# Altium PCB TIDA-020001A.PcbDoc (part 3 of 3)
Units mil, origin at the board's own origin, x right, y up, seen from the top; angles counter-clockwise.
Board outline 11050 x 5518 mil, 4 copper layers (Top Layer, PWR, GND, Bottom Layer), stack 61.434 mil thick; 283 components, 210 nets, 883 pads, 1184 vias.
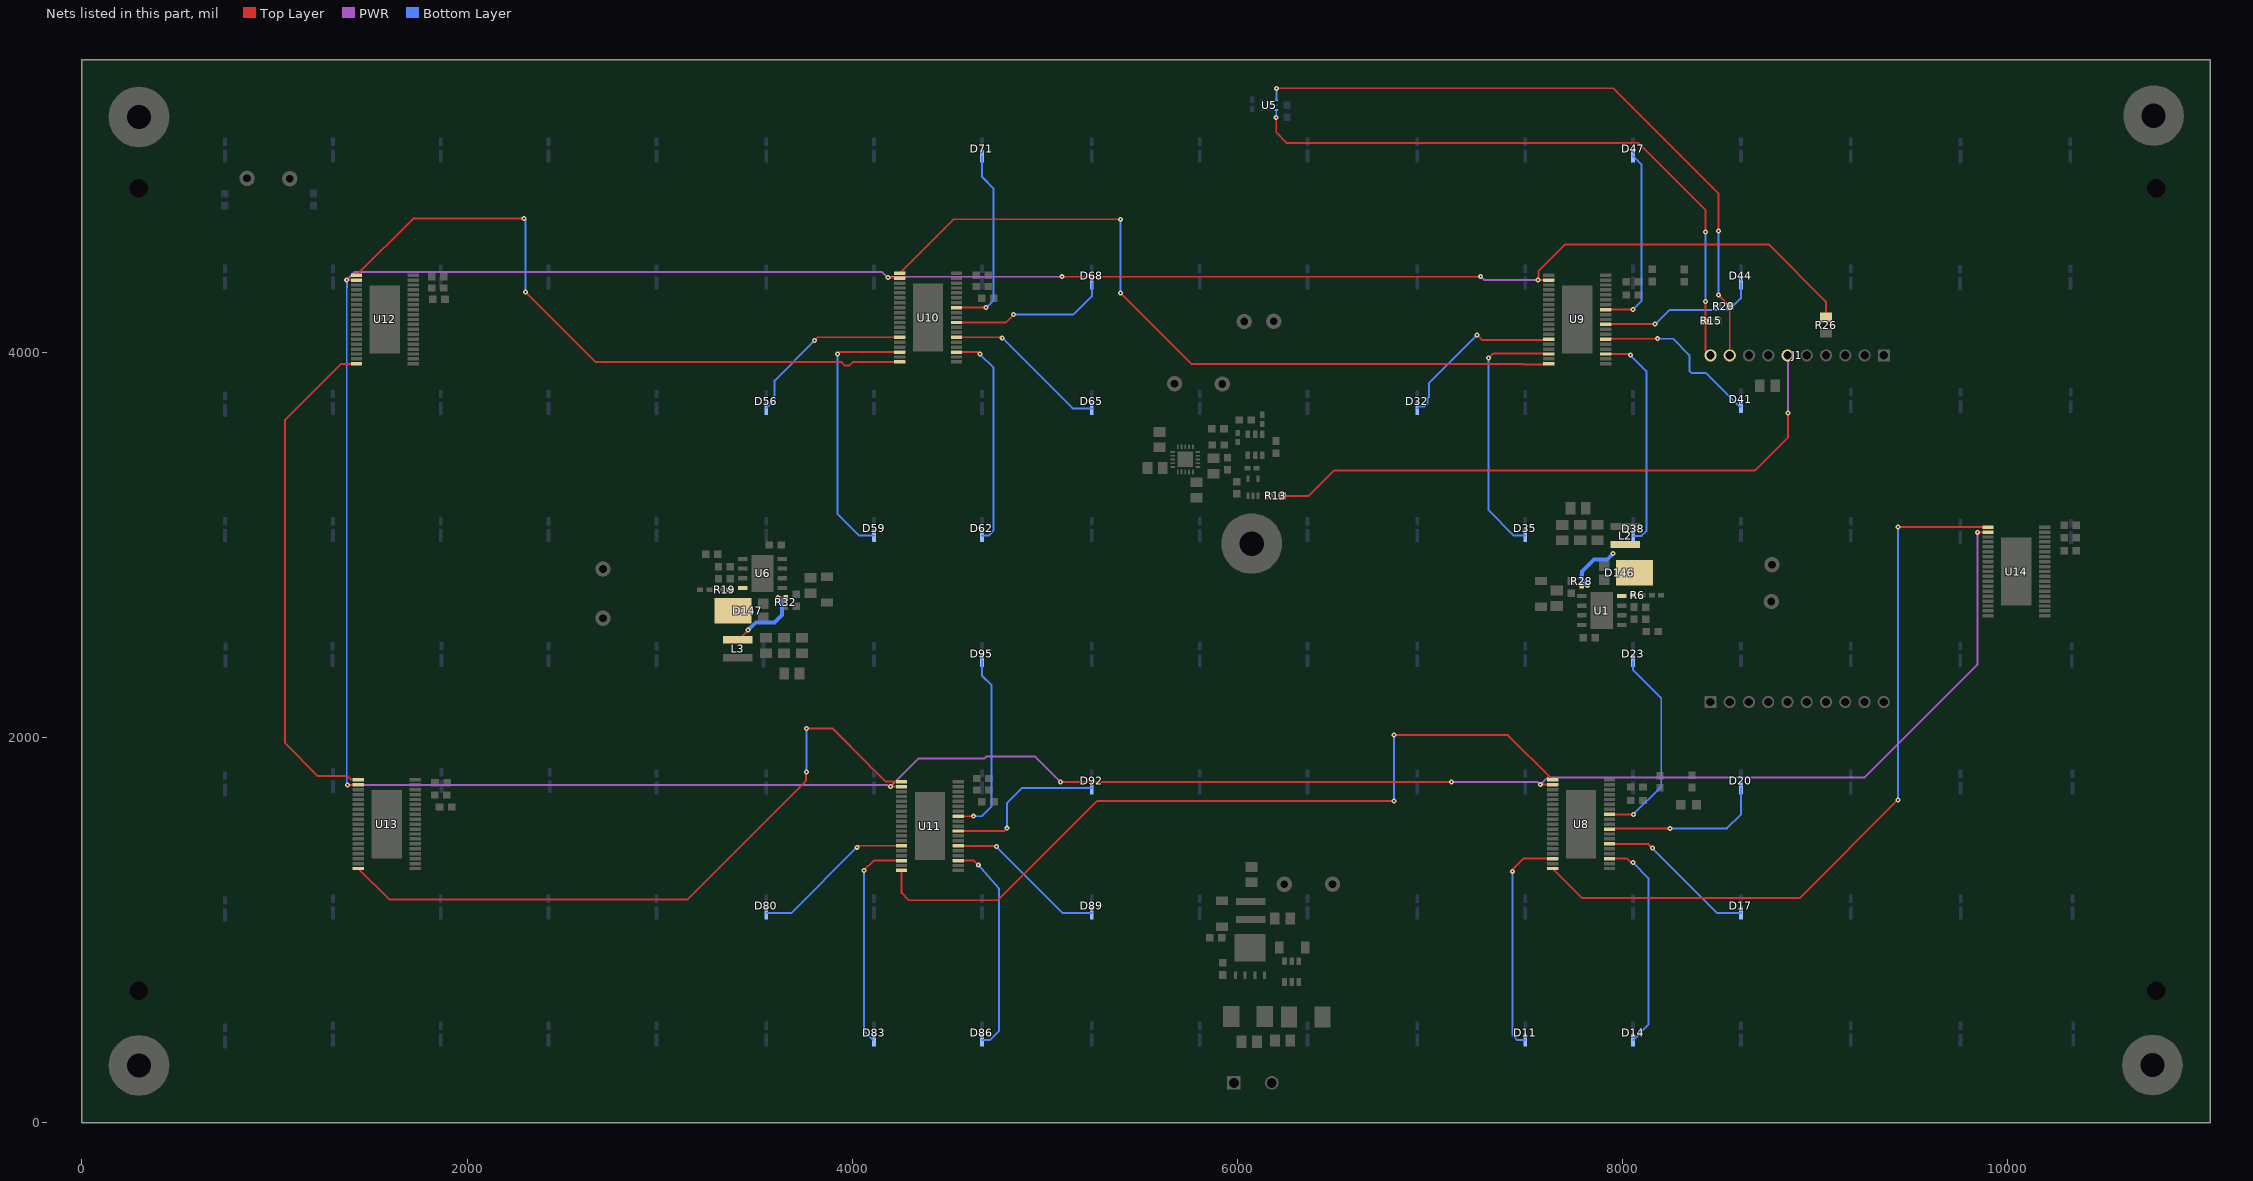
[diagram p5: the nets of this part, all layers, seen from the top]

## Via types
v1: diameter 20, hole 10, Top Layer to Bottom Layer, tented both sides, 504 vias
v2: diameter 26, hole 10, Top Layer to Bottom Layer, tented both sides, 472 vias
v3: diameter 19.68, hole 7.87, Top Layer to Bottom Layer, tented both sides, 205 vias
v4: diameter 34, hole 16, Top Layer to Bottom Layer, tented both sides, 2 vias
v5: diameter 19.68, hole 7.87, Top Layer to Bottom Layer, 1 vias

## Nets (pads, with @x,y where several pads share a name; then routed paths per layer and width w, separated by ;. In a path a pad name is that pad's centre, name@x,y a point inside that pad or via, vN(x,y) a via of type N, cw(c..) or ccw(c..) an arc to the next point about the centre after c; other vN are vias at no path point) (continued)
OUTR2/1: D32.1 U9.14 | length 911.9
  Top Layer w10: v2(7243.56,4089.71) 7270.99,4062.28 7580.99,4062.28 7582.2,4063.49 7612.07,4063.49 U9.14@7615.92,4067.35
  Bottom Layer w10: D32.1@6933.56,3708.21 6943.35,3718 6971,3718 6986.56,3733.56 6986.56,3761.21 6993.56,3768.21 6993.56,3839.71 v2(7243.56,4089.71)
OUTR2/2: D56.1 U10.14 | length 903.2
  Top Layer w10: v2(3803.56,4059.71) 3821.2,4077.35 U10.14@4245.92,4077.35
  Bottom Layer w10: D56.1@3553.56,3709.71 3596.43,3752.58 3596.43,3852.58 v2(3803.56,4059.71)
OUTR2/3: D80.1 U11.14 | length 847.2
  Top Layer w10: v2@4023.71,1429.71 v2(4023.56,1429.71) v2@4031.82,1437.97 ; v2@4032,1438 U11.14@4255.92,1437.35
  Bottom Layer w10: D80.1@3553.56,1088.21 3682.06,1088.21 v2(4023.56,1429.71)
OUTR3: D11.1 U8.17 | length 1171.5
  Top Layer w10: v2(7428.17,1305.1) 7423.56,1309.71 7484.43,1370.58 U8.17@7635.92,1370.58
  Bottom Layer w10: v2(7428.17,1305.1) 7428.17,453.6 7453.56,428.21 D11.1@7493.56,428.21
OUTR3/1: D35.1 U9.17 | length 1358.3
  Top Layer w10: v2(7303.56,3969.71) 7327.84,3993.99 7612.51,3993.99 U9.17@7615.92,3990.58
  Bottom Layer w10: v2(7303.56,3969.71) 7303.56,3179.71 7435.06,3048.22 D35.1@7493.56,3048.22
OUTR3/2: D59.1 U10.17 | length 1393
  Top Layer w10: v2(3923.56,3989.71) 3934.43,4000.58 U10.17@4245.92,4000.58
  Bottom Layer w10: v2(3923.56,3989.71) 3923.56,3159.71 4035.06,3048.21 D59.1@4113.56,3048.21
OUTR3/3: D83.1 U11.17 | length 1118.1
  Top Layer w10: v2(4060.41,1309.71) 4111.28,1360.58 U11.17@4255.92,1360.58
  Bottom Layer w10: v2(4060.41,1309.71) 4060.41,476.56 D83.1@4108.76,428.21
OUTR4: D14.1 U8.22 | length 1118.8
  Top Layer w10: U8.22@7931.2,1370.58 8022.69,1370.58 8043.56,1349.71 v2(8053.56,1349.71)
  Bottom Layer w10: D14.1@8053.56,428.21 8133.56,508.21 8133.56,1269.71 v2(8053.56,1349.71)
OUTR4/1: D38.1 U9.22 | length 1155.3
  Top Layer w10: U9.22@7911.2,3990.58 8033.83,3990.58 v2(8039.64,3984.76)
  Bottom Layer w10: v2(8039.64,3984.76) 8123.03,3901.37 8123.03,3075.77 ; D38.1@8054.9,3046.55 8096.81,3046.55 8124.37,3074.1
OUTR4/2: D62.1 U10.22 | length 1142.3
  Top Layer w10: U10.22@4541.2,4000.58 4541.61,4000.98 4641.73,4000 4652.56,4000 v2(4662.4,3990.16)
  Bottom Layer w10: v2(4662.4,3990.16) 4734.25,3918.31 4734.25,3074.8 4707.66,3048.21 D62.1@4673.56,3048.21
OUTR4/3: D86.1 U11.22 | length 1133.5
  Top Layer w10: U11.22@4551.2,1360.58 4631.68,1360.58 v2(4654.25,1338)
  Bottom Layer w10: v2@4646.31,1330.2 v2@4654.12,1338 ; v2(4654.25,1338) v2@4654.12,1338 ; D86.1@4673.56,428.21 4713.65,428.21 4760.83,475.39 4760.83,1216.54 4759.98,1216.54 v2@4654.12,1338
OUTR5: D17.1 U8.25 | length 831.1
  Top Layer w10: U8.25@7931.2,1447.35 8131.2,1447.35 v2(8153.56,1424.99)
  Bottom Layer w10: v2(8153.56,1424.99) 8490.33,1088.21 D17.1@8613.56,1088.21
OUTR5/1: D41.1 U9.25 | length 896.4
  Top Layer w10: U9.25@7911.2,4067.35 v2(8180.12,4069.88)
  Bottom Layer w10: v2(8180.12,4069.88) 8261.89,4069.88 8346.56,3985.21 8346.56,3902.67 8356.52,3892.71 8431.38,3892.71 8605.87,3718.21 D41.1@8613.56,3718.21
OUTR5/2: D65.1 U10.25 | length 855.3
  Top Layer w10: U10.25@4541.2,4077.35 4775.01,4077.35 v2(4778.54,4073.82)
  Bottom Layer w10: v2(4778.54,4073.82) 5144.15,3708.21 D65.1@5243.56,3708.21
OUTR5/3: D89.1 U11.25 | length 837
  Top Layer w10: U11.25@4551.2,1437.35 4744.06,1437.35 v2(4748.26,1433.14)
  Bottom Layer w10: v2(4748.26,1433.14) 5093.19,1088.21 D89.1@5243.56,1088.21
OUTR6: D20.1 U8.28 | length 852.1
  Top Layer w10: U8.28@7931.2,1524.12 7934.61,1527.53 v2(8245.05,1527.53)
  Bottom Layer w10: v2(8245.05,1527.53) 8540.32,1527.53 8614.17,1601.38 8614.17,1737.6 D20.1@8613.56,1738.21
OUTR6/1: D44.1 U9.28 | length 837
  Top Layer w10: U9.28@7911.2,4144.12 7913.93,4146.86 v2(8167.72,4146.86)
  Bottom Layer w10: v2(8167.72,4146.86) 8170.71,4146.86 8243.56,4219.71 8553.56,4219.71 8613.56,4279.71 D44.1@8613.56,4358.21
OUTR6/2: D68.1 U10.28 | length 828.8
  Top Layer w10: U10.28@4541.2,4154.12 4797.97,4154.12 4808.6,4164.75 4808.6,4165.56 4825.59,4182.54 4826.39,4182.54 4837.6,4193.75 v2(4837.6,4195.91)
  Bottom Layer w10: v2(4837.6,4195.91) 5149.76,4195.91 5223.56,4269.71 5243.56,4289.71 D68.1@5243.56,4358.22
OUTR6/3: D92.1 U11.28 | length 862
  Top Layer w10: U11.28@4551.2,1514.12 4789.15,1514.12 v2(4803.56,1528.53)
  Bottom Layer w10: v2(4803.56,1528.53) 4803.56,1659.71 4882.06,1738.21 D92.1@5243.56,1738.21
OUTR7: D23.1 U8.31 | length 1041.4
  Top Layer w10: U8.31@7931.2,1600.89 8054.62,1600.89 v2(8055.12,1600.39)
  Bottom Layer w10: D23.1@8054.27,2397.5 8054.27,2349 8199.8,2203.47 8199.8,1745.08 v2(8055.12,1600.39)
OUTR7/1: D47.1 U9.31 | length 974.5
  Top Layer w10: U9.31@7911.2,4220.89 v2(8052.38,4220.89)
  Bottom Layer w10: v2(8052.38,4220.89) 8096.43,4264.95 8096.43,4975.34 D47.1@8053.56,5018.21
OUTR7/2: D71.1 U10.31 | length 981.8
  Top Layer w10: U10.31@4541.2,4230.89 v2(4694.74,4230.89)
  Bottom Layer w10: D71.1@4673.56,5018.22 4673.56,4909.71 4733.56,4849.71 4733.56,4269.71 v2(4694.74,4230.89)
OUTR7/3: D95.1 U11.31 | length 970.4
  Top Layer w10: U11.31@4551.2,1590.89 v2(4628.94,1590.89)
  Bottom Layer w10: v2(4628.94,1590.89) 4672.38,1590.89 4723.56,1642.07 4723.56,2269.71 4673.56,2319.71 D95.1@4673.56,2398.21
SCK: R26.1 U8.2 U9.2 U10.2 U11.2 U12.2 U13.2 U14.2 | length 20609.9
  Top Layer w10: v2(1375.59,4374.72) 1425.64,4374.72 U12.2@1425.92,4374.43 ; v2(1379.92,1753.94) 1427.52,1753.94 1428.59,1755.01 1432.54,1751.05 U13.2@1435.92,1754.43 ; v2(4185.24,4388.01) 4242.35,4388.01 U10.2@4245.92,4384.43 ; v2(4197.83,1745.08) 4255.28,1745.08 U11.2@4255.92,1744.43 ; v2(5081.69,1767.72) v2(7110.24,1767.72) ; v2(5089.57,4391.73) 7261.81,4391.73 7262.8,4390.75 v2(7262.8,4392.72) ; v2@7561.02,4386.93 v2(7561.02,4375) 7615.36,4375 U9.2@7615.92,4374.43 ; v2@7561.86,4386.96 7561.86,4420.13 7700.79,4559.06 8758.86,4559.06 9055.12,4262.8 9055.12,4181.09 R26.1@9055.92,4180.3 ; v2(7571.85,1754.92) 7635.44,1754.92 U8.2@7635.92,1754.43 ; v2(9842.52,3064.96) 9888.65,3064.96 9892.89,3069.2 U14.2@9896.04,3066.05
  PWR w10: v2(1375.59,4374.72) 1418.19,4417.32 4152.56,4417.32 4186.02,4383.86 4185.04,4383.86 4185.24,4384.06 v2(4185.24,4388.01) 4188.97,4391.73 v2(5089.57,4391.73) ; v2(1379.92,1753.94) 4181.07,1753.94 4189.92,1745.08 v2(4197.83,1745.08) 4342.91,1890.16 4684.57,1890.16 4695,1900.59 4948.82,1900.59 v2(5081.69,1767.72) ; v2(7110.24,1767.72) 7559.06,1767.72 v2(7571.85,1754.92) 7609.9,1792.97 9256.48,1792.97 9842.52,2379.01 v2(9842.52,3064.96) ; v2(7262.8,4392.72) 7280.51,4375 v2(7561.02,4375)
  Bottom Layer w10: v2(1375.59,4374.72) 1375.59,4360.56 1377.36,4358.78 1377.36,4338.07 1375.59,4336.29 1375.59,1758.27 v2@1382.81,1751.05 ; v2(7571.85,1754.92) v2@7574.8,1757.87
SCLA: J1.9 R20.1 U5.4 | length 3452.5
  Top Layer w10: v2(6201.77,5370.08) 7949.8,5370.08 8498.03,4821.85 v2(8498.03,4628.94) ; v2(8498.03,4296.26) 8555.68,4238.61 J1.9@8555.68,3983.33
  Bottom Layer w10: U5.4@6201.03,5307.83 6201.77,5308.57 v2(6201.77,5370.08) ; v2(8498.03,4628.94) v2(8498.03,4296.26) v2@8500.98,4293.31
SDAA: J1.10 R15.1 U5.6 | length 3277.6
  Top Layer w10: v2(6201.03,5217.52) 6201.03,5141.49 6256.89,5085.63 8082.68,5085.63 8429.13,4739.17 8429.13,4624.02 v2(8430.12,4623.03) ; v2(8429.13,4262.8) R15.1@8429.13,4162.4 8429.13,4009.87 J1.10@8455.68,3983.33
  Bottom Layer w10: v2(6201.03,5217.52) U5.6@6201.03,5256.65 ; v2(8429.13,4262.8) 8430.12,4263.78 v2(8430.12,4623.03)
SDO8/SDI14: U8.19 U14.1 | length 3952.8
  Top Layer w10: U8.19@7635.92,1319.4 7789.97,1165.35 8918.31,1165.35 v2(9428.15,1675.2) ; v2(9428.15,3091.54) 9428.15,3092.52 9429.03,3091.64 U14.1@9896.04,3091.64
  Bottom Layer w10: v2(9428.15,1675.2) v2(9428.15,3091.54)
SDO9/SDI10: U9.19 U10.1 | length 4025.4
  Top Layer w10: U10.1@4245.92,4410.03 4525.86,4689.96 v2(5391.73,4689.96) ; v2(5391.73,4308.07) 5760.41,3939.4 7481.58,3939.4 7484.99,3935.99 7615.92,3935.99 U9.19@7615.92,3939.4
  Bottom Layer w10: v2(5391.73,4308.07) v2(5391.73,4689.96)
SDO10/SDI12: U10.19 U12.1 | length 3484.7
  Top Layer w10: U12.1@1425.92,4400.03 1719.8,4693.9 v2(2296.26,4693.9) ; v2(2304.13,4312.01) 2666.75,3949.4 3942.86,3949.4 3961.55,3930.71 3985.57,3930.71 4004.26,3949.4 U10.19@4245.92,3949.4
  Bottom Layer w10: v2(2296.26,4693.9) 2304.13,4686.02 v2(2304.13,4312.01)
SDO11/SDI8: U8.1 U11.19 | length 4163
  Top Layer w10: U11.19@4255.92,1309.4 4255.92,1192.9 4294.29,1154.53 4755.91,1154.53 5271.65,1670.28 v2(6812.01,1670.28) ; v2(6812.99,2011.81) 7404.14,2011.81 U8.1@7635.92,1780.03
  Bottom Layer w10: v2(6812.01,1670.28) 6812.99,1671.26 v2(6812.99,2011.81)
SDO12/SDI13: U12.19 U13.1 | length 2629.3
  Top Layer w10: U12.19@1425.92,3939.4 1346.88,3939.4 1054.13,3646.65 1054.13,1971.46 1225.98,1799.61 1378.54,1799.61 1398.12,1780.03 U13.1@1435.92,1780.03
SDO13/SDI11: U11.1 U13.19 | length 3529.2
  Top Layer w10: U13.19@1435.92,1319.4 1597.84,1157.48 3142.72,1157.48 3760.83,1775.59 3760.83,1818.9 v2(3761.81,1819.88) ; v2(3761.81,2046.26) 3898.51,2046.26 4089.17,1855.59 4089.17,1852.83 4103.82,1838.19 4106.58,1838.19 4174.69,1770.08 4187.48,1770.08 4208.19,1770.08 4208.24,1770.03 U11.1@4255.92,1770.03
  Bottom Layer w10: v2(3761.81,1819.88) v2(3761.81,2046.26)
SW1: D146.3 L2.1 R6.1 R28.2 U1.8 | length 334.1
  Top Layer w10: R28.2@7786.42,2788.39 7787.4,2787.4 v2(7815.94,2787.4) ; D146.3@8061.65,2855.32 D146.3@8061.65,2876.34
  Bottom Layer w20: v2(7815.94,2787.4) 7789.37,2813.98 7789.37,2862.16 7851.48,2924.27 7919.35,2924.27 v2(7948.82,2953.74)
SW2: D147.3 L3.1 R19.1 R32.2 U6.8 | length 424
  Top Layer w10: L3.1@3405.51,2506.89 3409.45,2506.89 v2(3459.65,2557.09) ; v2(3615.16,2725.53) 3656.36,2725.53 R32.2@3657.48,2724.41
  Bottom Layer w20: v2(3459.65,2557.09) 3498.72,2596.16 3596.16,2596.16 3634.84,2634.84 3634.84,2705.84 v2(3615.16,2725.53)
Temp_Out: J1.6 R13.2 | length 3179.2
  Top Layer w10: R13.2@6231.3,3253.94 6369.56,3253.94 6501.65,3386.03 8687.12,3386.03 8857.2,3556.11 v2(8857.2,3684.02) v2@8856.98,3684.24
  PWR w10: J1.6@8855.68,3983.33 8857.2,3981.81 v2(8857.2,3684.02)
pads on no net: H6.0 H7.0 H8.0 H9.0 H10.0 J2.1 J2.3 J2.4 J2.6 J2.7 J2.8 LBL1.0 U1.9@7891.73,2658.86 U3.2 U3.5 U3.6 U3.7 U3.9 U3.10 U3.11 U3.12 U6.9@3534.15,2851.35 U8. U8.5 U8.6 U9. U9.5 U9.6 U10. U10.5 U10.6 U11. U11.5 U11.6 U12. U12.5 U12.6 U12.7 U12.10 U12.13 U12.16 U12.23 U12.26 U12.29 U12.32 U13. U13.5 U13.6 U13.7 U13.10 U13.13 U13.16 U13.23 U13.26 U13.29 U13.32 U14. U14.5 U14.6 U14.7 U14.10 U14.13 U14.16 U14.23 U14.26 U14.29 U14.32
copper on no net:
  other v2: 6061.02,3519.69 6091.8,3519.55 6125,3520.67

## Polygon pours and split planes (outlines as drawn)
GND on Top Layer "TOP_LAYER_GND_P024" (solid, remove dead copper, pour order 24): 3242.13,2845.47 3430.12,2845.47 3437.99,2837.6 3437.99,2802.17 3312.01,2802.17 3287.4,2777.56 3287.4,2726.38 3235.24,2726.38 3229.33,2732.28 3229.33,2848.43
NetC18_1 on Top Layer "TOP_LAYER_NETC18_1_P022" (solid, remove dead copper, pour order 22): 5868.11,1279.53 5871.06,1276.57 6168.31,1276.57 6168.31,1118.11 5870.08,1118.11 5870.08,1272.64 5867.13,1275.59
GND on Top Layer "Layer 1 - Top Layer - GND" (solid, remove dead copper, pour order 62): -12.37,6.23 11037.63,6.23 11037.63,5506.23 -12.37,5506.23
GND on Top Layer "TOP_LAYER_GND_P002" (solid, remove dead copper, pour order 2): 3479.33,3026.05 3597.38,3026.05 3608.74,2628.94 3876.97,2628.94 3876.97,2505.91 3541.34,2505.91 3511.81,2535.43 3513.78,2537.4 3513.78,2698.82 3485.24,2698.82 3479.33,2704.72
SW1 on Top Layer "TOP_LAYER_SW1_P004" (solid, remove dead copper, pour order 4): 7971.46,2710.63 7962.6,2719.49 7968.5,2725.39 7968.5,2833.66 8040.35,2833.66 8028.54,2821.85 8028.54,2710.63
GND on Top Layer "TOP_LAYER_GND_P006" (solid, remove dead copper, pour order 6): 7941.93,2660.43 8194.88,2660.43 8191.93,2663.39 8191.93,2702.76 8175.2,2719.49 8175.2,2771.65 8162.4,2771.65 8098.43,2707.68 7941.93,2707.68
GND on Top Layer "TOP_LAYER_GND_P018" (solid, remove dead copper, pour order 18): 7951.77,2686.02 7951.77,2644.69 8198.82,2644.69 8198.82,2684.06 8178.15,2704.72 8178.15,2768.7 8146.65,2768.7 8122.05,2744.09 8122.05,2701.77 8046.26,2701.77 8029.53,2685.04
GND on Top Layer "TOP_LAYER_GND_P020" (solid, remove dead copper, pour order 20): 7834.65,2432.09 7834.65,2881.89 7802.17,2914.37 7794.29,2906.5 7632.87,2906.5 7632.87,2706.69 7630.91,2704.72 7628.94,2706.69 7545.28,2706.69 7545.28,2738.19 7465.55,2738.19 7465.55,2837.6 7536.42,2908.46 7729.33,3061.91 7900.49,3061.91 7980.81,3054.63 7942.91,2900.11 7942.91,2739.17 7942.91,2527.56 7927.17,2527.56 7847.44,2447.83 7845.47,2449.8 7816.93,2449.8
GND on Top Layer "TOP_LAYER_GND_P058" (solid, remove dead copper, pour order 58): 6107.28,274.61 6107.28,116.14 6108.27,115.16 6129.92,136.81 6500.98,136.81 6500.98,641.73 6494.09,648.62 6488.19,642.72 6397.64,642.72 6397.64,480.32 6380.91,463.58 6243.11,463.58 6243.11,384.84 6245.08,382.87 6222.44,360.24 6109.25,360.24
GND on Bottom Layer "Layer 4 - Bottom Layer - GND " (solid, remove dead copper, pour order 76): 0,0 4626.97,0 7448.82,0 11050,0 11035.84,5506.03 -14.16,5506.03
GND on GND "Layer 3 - GND - GND" (solid, remove dead copper, pour order 74): -13,30 5887,30 11027,30 11027,5500 -13,5500
Buck1_4V on PWR "PWR_BUCK1_4V_P040" (solid, remove dead copper, pour order 40): 6289.37,5485.24 6289.37,5400.59 6289.37,0 11050,0 11050,5485.24
buck2_4V on PWR "PWR_BUCK2_4V_P054" (solid, remove dead copper, pour order 54): 6008.86,5474.41 6008.86,5363.19 6008.86,27.74 27.74,27.74 0,5518

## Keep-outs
Keep-Out Layer:
  text ".Layer_Name" at 577,-858.49 h27.56

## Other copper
Top Layer:
  rectangle net GND: 7840.55,2746.06 7930.96,2907.13
  rectangle net buck2_4V: 4525.56,1764.03 4562.01,1857.28
  rectangle net NetC4_1: 7303.15,2623.03 7474.41,2810.04
  rectangle net GND: 4708.24,4258.86 4756.89,4426.89
  rectangle net GND: 8054.13,4320.87 8232.28,4394.69
  rectangle net GND: 8061.02,4269.98 8110.18,4397.64
  rectangle net GND: 4704.72,1646.65 4756.89,1817.91
  rectangle net GND: 10329.72,2942.63 10392.72,3125.7
  rectangle net Buck1_4V: 7880.19,4391.73 7940.94,4469.49
  rectangle net Buck1_4V: 7900.59,1780.03 7960.63,1858.27
  rectangle net buck2_4V: 1688.26,4391.73 1747.05,4477.89
  rectangle net buck2_4V: 4509.84,4401.57 4570.87,4486.22
  rectangle net buck2_4V: 1712.6,1772.64 1760.83,1854.33
  rectangle net NetC14_1: 7623.03,3067.91 8113.19,3147.64
  region net Buck1_4V: 7758.86,3155.51 7758.86,3263.78 7578.74,3263.78 7578.74,3155.51
  region net NetC17_1: 6222.44,963.58 6222.44,1101.38 5972.44,1101.38 5972.44,963.58
  region net NetC17_1: 5979.33,809.06 5979.33,890.75 5893.33,890.75 5893.33,809.06
  rectangle net 3V3: 5743.93,3358.98 5812.93,3387.98
  rectangle net 3V3: 5786.98,3365.98 5814.93,3407.74
  region net GND: 1942.62,1610.24 1942.62,1790.06 1892.22,1790.06 1892.22,1610.24
  rectangle net Buck1_4V: 10165.68,3085.65 10219,3172.24
  rectangle net 3V3: 5747.93,3299.21 6059.57,3374.3
  rectangle net 3V3: 5791.2,3355.98 5960.93,3408.47
  rectangle net NetC10_2: 5847.7,3417.13 5972.4,3463.47
  rectangle net NetC10_2: 5847.16,3422.47 5886.7,3524.47
  rectangle net 3V3: 5843.47,3324.31 6119.09,3359.25
  region net 3V3: 6062.25,3393.3 6062.25,3486.94 6037.58,3486.94 6037.58,3393.3
  region net NetR4_1: 6099.75,3552.11 6099.75,3662.3 6083.58,3662.3 6083.58,3552.11
  region net 3V3_LS: 6023.58,3569.06 6023.58,3666.3 5988.78,3666.3 5988.78,3569.06
  region net 3V3_LS: 6065.58,3563.3 6065.58,3593.3 5988.77,3593.3 5988.77,3563.3
  rectangle net 3V3: 6035.94,3236.22 6062.99,3418.14
  region net ANODE: 6060.04,138.78 6060.04,777.56 5871.06,777.56 5871.06,138.78
  region net NetD145_2: 6288.39,490.16 6288.39,599.16 6087.39,599.16 6087.39,490.16
  region net NetC3_2: 6236.22,387.71 6236.22,455.71 6076.22,455.71 6076.22,387.71
  region net ANODE: 6110.24,651.57 6110.24,788.79 5895.67,788.79 5895.67,651.57
  region net ANODE: 6374.02,819.69 6374.02,949.07 6306.41,949.07 6306.41,819.69
  region net ANODE: 6492.13,702.76 6053.69,702.76 6053.69,627.71 6492.13,627.71
  region net ANODE: 6261.81,680.12 6261.81,757.12 6218.13,757.12 6218.13,680.12
  region net ANODE: 6496.06,656.5 6496.06,947.83 6345.47,947.83 6345.47,656.5
  rectangle net NetC10_2: 5782.93,3437.98 5913.93,3448.98
  rectangle net Buck1_4V: 5585.33,3312.64 5710.87,3386.3
  rectangle net Buck1_4V: 5637.06,3364.24 5674.46,3430.59
  rectangle net buck2_4V: 3699.82,2263.78 3884.84,2373.03
  rectangle net GND: 6237.2,963.58 6320.87,1068.9
  rectangle net NetC4_1: 5886.81,1303.15 6278.54,1523.62
  rectangle net NetC4_1: 4000,2709.65 4122.05,2901.57
  rectangle net NetC4_1: 3604.33,2803.15 4017.72,2900.59
  rectangle net NetC4_1: 7308.07,2615.16 7821.85,2707.68
  rectangle net NetC14_1: 7774.33,3140.75 7842.7,3228.87
  rectangle net NetC26_1: 3328.74,2380.53 3818.9,2462.83
  rectangle net NetC26_1: 3616.14,2300.2 3672.24,2396.65
  region net 3V3_LS: 7885.56,4329.26 7885.56,4317.26 7978.1,4314.96 7978.1,4333.38
  region net SW1: 7975.05,2724.24 7977.48,2721.82 8036.78,2721.82 8079.72,2764.76 8174.21,2764.76 8174.21,3022.64 7936.02,3022.64 7936.02,2941.93 7960.08,2917.88 7960.08,2792.45 7975.05,2754.34
  region net 3V3_LS: 1695.56,4315.09 1802.93,4314.82 1824.8,4336.69 1836.34,4336.69 1836.34,4448.82 1794.38,4448.82 1794.38,4343.95 1781.14,4330.71 1695.56,4330.71
  region net 3V3_LS: 7906.91,1709.26 7906.91,1697.26 7995.08,1694.88 7999.02,1698.82 7995.08,1712.6 7907.3,1709.65
  region net 3V3_LS: 10249.02,3176.18 10265.29,3159.91 10265.29,3022.41 10172.79,3022.41 10165.68,3015.29 10165.68,3008.87 10296.24,3008.87 10294.29,3010.83 10294.29,3177.17
  region net SW2: 3455.71,2786.42 3453.74,2788.39 3378.94,2788.39 3328.74,2738.19 3286.42,2738.19 3286.42,2491.14 3487.2,2491.14 3487.2,2570.93 3476.38,2581.75 3476.38,2690.86 3455.71,2743.45
  text ".Layer_Name" at 577,-858.49 h27.56
PWR:
  rectangle net NetC4_1: 4005.91,2709.65 5884.84,2895.67
  rectangle net NetC4_1: 6084.65,2634.84 7435.04,2812.01
  region net NetC4_1: 5879.92,2812.01 5879.92,1379.92 6272.64,1379.92 6272.64,2812.01
  rectangle net Buck1_4V: 5585.33,3312.64 5669,3373.67
  region net NetC4_1: 5970.47,2809.55 5884.84,2809.55 5884.84,2895.18
Bottom Layer:
  rectangle net Buck1_4V: 9727,1144.65 9784.56,1234.65
  rectangle net buck2_4V: 4083.19,1786.97 4140.75,1887.8
  rectangle net buck2_4V: 699.96,5059.05 793.46,5182.08
  rectangle net buck2_4V: 1259.96,5059.05 1353.46,5182.08
  rectangle net buck2_4V: 1819.96,5059.05 1913.46,5182.08
  rectangle net buck2_4V: 2379.96,5059.05 2473.46,5182.08
  rectangle net Buck1_4V: 10309.12,1142.33 10366.68,1232.33
  rectangle net buck2_4V: 2396,1139.71 2453.56,1229.71
  rectangle net buck2_4V: 2956,1139.71 3013.56,1229.71
  rectangle net buck2_4V: 3526,1139.71 3583.56,1229.71
  rectangle net buck2_4V: 4086,1139.71 4143.56,1229.71
  rectangle net buck2_4V: 4646,1139.71 4703.56,1229.71
  rectangle net buck2_4V: 5216,1139.71 5273.56,1229.71
  rectangle net buck2_4V: 5776,1139.71 5833.56,1229.71
  rectangle net Buck1_4V: 6336,1139.71 6393.56,1229.71
  rectangle net Buck1_4V: 6906,1139.71 6963.56,1229.71
  rectangle net Buck1_4V: 7466,1139.71 7523.56,1229.71
  rectangle net Buck1_4V: 8026,1139.71 8083.56,1229.71
  rectangle net buck2_4V: 1836,1139.71 1893.56,1229.71
  rectangle net buck2_4V: 1276,1139.71 1333.56,1229.71
  rectangle net buck2_4V: 716,1129.71 773.56,1219.71
  rectangle net Buck1_4V: 8586,1139.71 8643.56,1229.71
  rectangle net Buck1_4V: 9156,1139.71 9213.56,1229.71
  rectangle net Buck1_4V: 9154.05,2441.5 9211.61,2543.31
  rectangle net Buck1_4V: 8585.16,2444.45 8642.72,2540.35
  rectangle net buck2_4V: 717.05,2444.45 774.61,2544.29
  rectangle net buck2_4V: 1273.85,2451.77 1331.41,2549.21
  rectangle net buck2_4V: 1837.12,2447.4 1894.68,2545.28
  rectangle net buck2_4V: 2396.18,2441.5 2453.74,2546.26
  rectangle net buck2_4V: 2956.22,2442.48 3013.78,2543.31
  rectangle net buck2_4V: 4085.16,2444.45 4142.72,2542.32
  rectangle net buck2_4V: 4645.2,2439.53 4702.76,2540.35
  rectangle net buck2_4V: 5215.08,2442.48 5272.64,2543.31
  rectangle net buck2_4V: 5776.1,2443.46 5833.66,2543.31
  rectangle net Buck1_4V: 6334.17,2442.48 6391.73,2554.13
  rectangle net Buck1_4V: 6904.05,2443.46 6961.61,2547.24
  rectangle net Buck1_4V: 7465.08,2440.51 7522.64,2538.39
  rectangle net Buck1_4V: 8023.15,2443.46 8080.71,2546.26
  rectangle net Buck1_4V: 9720.98,2449.8 9778.54,2548.66
  rectangle net Buck1_4V: 10300.71,2446.42 10358.27,2545.28
  rectangle net Buck1_4V: 9156.02,3090.12 9213.58,3200.73
  rectangle net Buck1_4V: 8586.14,3090.12 8643.7,3201.71
  rectangle net buck2_4V: 715.08,3095.04 772.64,3191.93
  rectangle net buck2_4V: 1275.12,3096.02 1332.68,3191.93
  rectangle net buck2_4V: 1834.17,3098.98 1891.73,3188.98
  rectangle net buck2_4V: 2394.21,3097.01 2451.77,3200.79
  rectangle net buck2_4V: 2955.23,3095.04 3012.8,3200.73
  rectangle net buck2_4V: 3524.13,3091.1 3581.69,3203.68
  rectangle net buck2_4V: 4085.16,3095.04 4142.72,3197.78
  rectangle net buck2_4V: 4644.21,3096.02 4701.77,3194.88
  rectangle net buck2_4V: 5215.08,3097.99 5272.64,3194.88
  rectangle net buck2_4V: 5777.08,3097.01 5834.65,3197.83
  rectangle net Buck1_4V: 6335.16,3092.09 6392.72,3199.75
  rectangle net Buck1_4V: 6905.51,3093.07 6963.07,3193.9
  rectangle net Buck1_4V: 7466.06,3096.84 7523.62,3201.77
  rectangle net Buck1_4V: 8027.08,3099.96 8084.65,3204.67
  rectangle net Buck1_4V: 9723.03,3084.06 9780.59,3179.13
  rectangle net Buck1_4V: 10301.69,3082.24 10359.25,3178.15
  rectangle net Buck1_4V: 9153.29,3770.21 9210.85,3870.08
  rectangle net Buck1_4V: 8587.12,3760.97 8644.68,3856.3
  rectangle net buck2_4V: 715.08,3750.22 772.64,3849.41
  rectangle net buck2_4V: 1275.12,3762.8 1332.68,3863.19
  region net buck2_4V: 1834.87,3759.23 1892.43,3759.93 1891.26,3856.65 1833.7,3855.95
  rectangle net buck2_4V: 2393.23,3759.84 2450.79,3857.28
  rectangle net buck2_4V: 2957.12,3760.97 3014.68,3852.36
  rectangle net buck2_4V: 3525.12,3759.84 3582.68,3873.03
  rectangle net buck2_4V: 4083.19,3758.86 4140.75,3860.84
  rectangle net buck2_4V: 4646.65,3761.21 4704.21,3859.25
  rectangle net buck2_4V: 5210.09,3755.91 5272.64,3874.02
  rectangle net buck2_4V: 5772.16,3762.8 5829.72,3876.7
  rectangle net Buck1_4V: 6333.19,3759.84 6390.75,3871.06
  rectangle net Buck1_4V: 6905.04,3761.81 6962.6,3862.2
  rectangle net Buck1_4V: 7463.11,3760.39 7520.67,3865.16
  rectangle net Buck1_4V: 8023.56,3759.84 8081.12,3862.2
  rectangle net Buck1_4V: 9724.92,3769.25 9782.48,3859.25
  rectangle net Buck1_4V: 10297.75,3768.27 10355.32,3871.06
  rectangle net Buck1_4V: 9152.08,4402.13 9209.65,4511.75
  rectangle net Buck1_4V: 8584.17,4406.06 8641.73,4508.86
  rectangle net buck2_4V: 713.58,4400.16 771.14,4502.95
  rectangle net buck2_4V: 1275.12,4405.08 1332.68,4514.76
  rectangle net buck2_4V: 1835.16,4400.16 1892.72,4508.86
  rectangle net buck2_4V: 2394.21,4401.14 2451.77,4498.03
  rectangle net buck2_4V: 2954.25,4404.09 3011.81,4515.69
  rectangle net buck2_4V: 3524.13,4400.16 3581.69,4510.77
  rectangle net buck2_4V: 4085.16,4403.11 4142.72,4510.77
  rectangle net buck2_4V: 4646.18,4407.05 4703.74,4511.81
  rectangle net buck2_4V: 5215.08,4400.16 5272.64,4500
  rectangle net buck2_4V: 5773.15,4400.16 5830.71,4500
  rectangle net Buck1_4V: 6333.71,4400.68 6391.28,4502.5
  rectangle net Buck1_4V: 6905.04,4401.14 6962.6,4506.89
  rectangle net Buck1_4V: 7465.08,4400.16 7522.64,4498.03
  rectangle net Buck1_4V: 8023.15,4402.13 8080.71,4505.91
  rectangle net Buck1_4V: 9722.95,4405.08 9780.51,4508.86
  rectangle net Buck1_4V: 10293.82,4400.16 10351.38,4499.02
  rectangle net Buck1_4V: 9156,472.82 9213.56,581.69
  rectangle net Buck1_4V: 8586,472.82 8643.56,577.76
  rectangle net buck2_4V: 716,462.82 773.56,562.01
  rectangle net buck2_4V: 1276,472.82 1333.56,575.79
  rectangle net buck2_4V: 1836,472.82 1893.56,576.77
  rectangle net buck2_4V: 2396,472.82 2453.56,577.76
  rectangle net buck2_4V: 2956,472.82 3013.56,574.8
  rectangle net buck2_4V: 3526,472.82 3583.56,573.82
  rectangle net buck2_4V: 4086,472.82 4143.56,572.83
  rectangle net buck2_4V: 4646,472.82 4703.56,580.71
  rectangle net buck2_4V: 5216,472.82 5273.56,577.76
  rectangle net buck2_4V: 5775.12,479.33 5832.68,588.2
  rectangle net Buck1_4V: 6336,472.82 6393.56,573.82
  rectangle net Buck1_4V: 6906,472.82 6963.56,575.79
  rectangle net Buck1_4V: 7466,472.82 7523.56,579.72
  rectangle net Buck1_4V: 8024.13,477.74 8081.69,585.63
  rectangle net Buck1_4V: 9725,473.82 9782.56,582.68
  rectangle net Buck1_4V: 10310,471.82 10367.56,576.77
  rectangle net Buck1_4V: 10305.63,1778.11 10363.19,1884.84
  rectangle net Buck1_4V: 9724.92,1784.02 9782.48,1883.86
  rectangle net Buck1_4V: 8025.12,1784.02 8082.68,1883.86
  rectangle net Buck1_4V: 7465.08,1784.02 7522.64,1885.83
  rectangle net Buck1_4V: 6904.05,1781.06 6961.61,1883.86
  rectangle net Buck1_4V: 6334.17,1782.05 6391.73,1889.76
  rectangle net buck2_4V: 5775.12,1789.92 5832.68,1890.75
  rectangle net buck2_4V: 5215.08,1785 5272.64,1892.72
  rectangle net buck2_4V: 4644.21,1786.97 4701.77,1885.83
  rectangle net buck2_4V: 3526.1,1785 3583.66,1895.67
  rectangle net buck2_4V: 2956.69,1785.98 3014.25,1888.78
  rectangle net buck2_4V: 2401.1,1788.94 2458.66,1896.65
  rectangle net buck2_4V: 1836.14,1788.94 1893.7,1894.68
  rectangle net buck2_4V: 1274.13,1790.73 1331.69,1901.57
  rectangle net buck2_4V: 714.09,1776.14 771.65,1878.94
  rectangle net Buck1_4V: 8583.19,1779.09 8640.75,1904.53
  rectangle net Buck1_4V: 9155.04,1784.02 9212.6,1897.64
  rectangle net buck2_4V: 2941.99,5067.85 3035.49,5210.63
  rectangle net buck2_4V: 3511.99,5067.85 3605.49,5194.76
  rectangle net buck2_4V: 4071.99,5067.85 4165.49,5190.88
  rectangle net buck2_4V: 4631.89,5064.96 4725.39,5209.65
  rectangle net buck2_4V: 5195.87,5063.98 5289.37,5203.74
  rectangle net buck2_4V: 5759.84,5065.94 5853.35,5208.66
  rectangle net Buck1_4V: 6319.96,5059.05 6413.46,5182.08
  rectangle net Buck1_4V: 6889.96,5059.05 6983.46,5185.96
  rectangle net Buck1_4V: 7449.96,5059.05 7543.46,5189.96
  rectangle net Buck1_4V: 8009.96,5059.05 8103.46,5191.93
  rectangle net Buck1_4V: 8569.96,5059.06 8663.46,5185.96
  rectangle net Buck1_4V: 9139.96,5059.05 9233.46,5193.9
  rectangle net Buck1_4V: 9710.08,5056.67 9803.58,5179.7
  rectangle net Buck1_4V: 10280.08,5058.67 10373.58,5189.96
  text ".Layer_Name" at 577,-858.49 h27.56

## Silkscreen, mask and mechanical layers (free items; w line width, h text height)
Top Overlay:
  text "+" at 175,4789 h27.56 r90
  text "-" at 159,4286 h27.56 r90
  text "'.PRJ_Number'-.PCB_Rev" at 10854.33,3115.16 h108.27 r90
  text "-" at 6388.78,195.87 h72.83
  text "+" at 5725.39,182.09 h72.83
  text ".Layer_Name" at 577,-858.49 h27.56
Bottom Overlay:
  text ".Layer_Name" at 577,-858.49 h27.56
Top Paste:
  text ".Layer_Name" at 577,-858.49 h27.56
Bottom Paste:
  text ".Layer_Name" at 577,-858.49 h27.56
Top Solder:
  text ".Layer_Name" at 577,-858.49 h27.56
  text ".Layer_Name" at 577,-858.49 h27.56
Bottom Solder:
  text ".Layer_Name" at 577,-858.49 h27.56
Drill Guide:
  text ".Layer_Name" at 577,-858.49 h27.56
M1 Board Outline:
  text ".Layer_Name" at 577,-858.49 h27.56
M2 Board Dimensions:
  rectangle: 0,-275 125,-150
  rectangle: 125,-400 500,-275
  lines w7: 0,-275 1000,-275 ; 125,-400 125,-150 ; 250,-400 250,-150 ; 500,-400 500,-150 ; 750,-400 750,-150 ; 0,-400 1000,-400 1000,-150 0,-150 0,-400
  text ".Layer_Name" at 577,-858.49 h27.56
M3 3D STEP Top:
  text ".Layer_Name" at 577,-858.49 h27.56
M4 3D STEP Bottom:
  text ".Layer_Name" at 577,-858.49 h27.56
M5 Assembly Top:
  lines w10: -292,-930.17 6308,-930.17 ; -292,-726.83 6310,-726.83 ; -292,-523.5 -292,-1133.5 3713,-1133.5 6310,-1133.5 6310,-523.5 -291.5,-523.5 -291.5,-1133.5 1284,-1133.5 ; 2173,-1133.5 2173,-523.5 ; 3440,-726.83 3440,-523.5 ; 4280,-726.83 4280,-523.5 ; 4902,-1140 4902,-937.17
  text "COMPONENTS MARKED 'DNP' SHOULD NOT BE POPULATED." at 1153.5,-318.5 h27.56
  text "ASSEMBLY VARIANT:" at 1153,-434 h27.56
  text ".VariantName" at 2189,-434 h27.56
  text "PCB VIEWED FROM TOP SIDE" at -228.5,-655.67 h27.56
  text "BOARD #:" at 2248,-655.67 h27.56
  text ".PRJ_Number" at 2793.5,-655.67 h27.56
  text "REV:" at 3638,-655.67 h27.56
  text ".PCB_Rev" at 3929.5,-655.67 h27.56
  text "SVN REV:" at 4476,-655.67 h27.56
  text ".VersionControl_RevNumber" at 4982,-655.67 h27.56
  text "TID #:" at 2248,-859 h27.56
  text ".TID" at 2793.5,-859 h27.56
  text "PLOT NAME =" at -228.5,-1064.34 h27.56
  text ".plot_File_Name" at 577,-1064.34 h27.56
  text "GENERATED    :" at 2250,-1064.34 h27.56
  text ".Print_Date" at 3119.5,-1064.34 h27.56
  text ".Print_Time" at 3848.5,-1064.34 h27.56
  text "TEXAS INSTRUMENTS" at 5113,-1064.34 h27.56
M6 Assembly Bottom:
  lines w10: -292.5,-727.33 6309.5,-727.33 ; -290.5,-930.67 6309.5,-930.67 ; 1115.5,-1140.5 1115.5,-937.67 ; 1737.5,-727.33 1737.5,-524 ; 2577.5,-727.33 2577.5,-524 ; 3844.5,-1134 3844.5,-524 ; 4733.5,-1134 6309,-1134 6309,-524 -292.5,-524 -292.5,-1134 2304.5,-1134 6309.5,-1134 6309.5,-524
  text "COMPONENTS MARKED 'DNP' SHOULD NOT BE POPULATED." at 6102,-318 h27.56
  text ".VariantName" at 5058,-434 h27.56
  text "ASSEMBLY VARIANT:" at 6097,-434 h27.56
  text ".VersionControl_RevNumber" at 1035.5,-656.17 h27.56
  text "SVN REV:" at 1541.5,-656.17 h27.56
  text ".PCB_Rev" at 2088,-656.17 h27.56
  text "REV:" at 2379.5,-656.17 h27.56
  text ".PRJ_Number" at 3224,-656.17 h27.56
  text "BOARD #:" at 3769.5,-656.17 h27.56
  text "PCB VIEWED FROM BOTTOM SIDE" at 6246,-656.17 h27.56
  text ".TID" at 3224,-859.5 h27.56
  text "TID #:" at 3769.5,-859.5 h27.56
  text "TEXAS INSTRUMENTS" at 904.5,-1064.84 h27.56
  text ".Print_Time" at 2169,-1064.84 h27.56
  text ".Print_Date" at 2898,-1064.84 h27.56
  text "GENERATED    :" at 3767.5,-1064.84 h27.56
  text ".plot_File_Name" at 5440.5,-1064.84 h27.56
  text "PLOT NAME =" at 6246,-1064.84 h27.56
M9 Title Sheet:
  drawing of 57 lines, arcs and shapes, not listed
  text "1" at 739.84,8036.5 h27.56
  text "2" at 3235.5,8036.5 h27.56
  text "3" at 5724.84,8036.5 h27.56
  text "4" at 8231.51,8036.5 h27.56
  text "5" at 10730.5,8036.5 h27.56
  text "6" at 13235.5,8036.5 h27.56
  text "A" at -416.5,6893.5 h27.56
  text "A" at 14383.5,6893.5 h27.56
  text "B" at -416.5,4513.5 h27.56
  text "B" at 14383.5,4513.5 h27.56
  text "C" at -416.5,2138.5 h27.56
  text "C" at 14383.5,2138.5 h27.56
  text "PROJECT TITLE:" at 11343.5,277.5 h27.56
  text ".PRJ_Title" at 11393.5,144.17 h27.56
  text "DESIGNED FOR:" at 11343.5,-23.5 h27.56
  text ".PRJ_Customer" at 11393.5,-163.5 h27.56
  text "D" at -416.5,-231.5 h27.56
  text "D" at 14383.5,-231.5 h27.56
  text "FILE NAME:" at 11343.5,-323.5 h27.56
  text ".PCB_File_Name_No_Path" at 11393.5,-443.5 h27.56
  text "Texas Instruments (TI) and/or its licensors do not warrant the accuracy or completeness of this specification" at 6374,-605.34 h27.56
  text "ENGINEER:" at 11343.5,-613.5 h27.56
  text "LAYOUT BY:" at 12848.5,-613.5 h27.56
  text "or any information contained therein. TI and/or its licensors do not warrant that this design will meet" at 6329.01,-718 h27.56
  text ".PRJ_Engineer" at 11393.5,-768.49 h27.56
  text ".PCB_Layout" at 12899,-768.49 h27.56
  text "the specifications, will be suitable for your application or fit for any particular purpose, or will operate in" at 6329.01,-830.67 h27.56
  text ".Layer_Name" at 577,-858.49 h27.56
  text "ALTIUM DESIGNER VERSION:" at 12848.5,-923.5 h27.56
  text "an implementation. TI and/or its licensors do not warrant that the design is production worthy. You should" at 6329.01,-943.33 h27.56
  text "completely validate and test your design implementation to confirm the system functionality for your application." at 6374,-1056 h27.56
  text ".print_Scale" at 11393.5,-1056.83 h27.56
  text ".Application_BuildNumber" at 12899,-1056.83 h27.56
  text "1" at 739.84,-1263.5 h27.56
  text "2" at 3235.5,-1263.5 h27.56
  text "3" at 5724.84,-1263.5 h27.56
  text "4" at 8231.51,-1263.5 h27.56
  text "5" at 10730.5,-1263.5 h27.56
  text "6" at 13235.5,-1263.5 h27.56
M10 Fab Notes:
  drawing of 189 lines, arcs and shapes, not listed
  text "DESIGN INFORMATION" at 12382.02,6356.17 h27.56
  text "MIN. TRACK WIDTH:" at 11737.46,6224.05 h27.56
  text "8" at 12833.7,6224.05 h27.56
  text "MIL" at 12988.46,6224.05 h27.56
  text "MIN. CLEARANCE:" at 11737.46,6099.92 h27.56
  text "0.2" at 12773.7,6099.93 h27.56
  text "mm" at 12988.46,6099.92 h27.56
  text "MIN. VIA PAD SIZE:" at 11737.46,5975.8 h27.56
  text "24" at 12803.71,5975.8 h27.56
  text "MIL" at 12988.46,5975.8 h27.56
  text "0.05mm (2MIL)" at 12432.46,5845.9 h27.56
  text "MINIMUM ANNULAR RING" at 11408.23,5837.67 h27.56
  text "EXTERNAL" at 13140.46,5837.67 h27.56
  text "PER" at 11608.23,5727.55 h27.56
  text "IPC-D-275 CLASS 2 LEVEL C" at 11828.23,5727.54 h27.56
  text "MIL, HOLES" at 13316.46,5627.07 h27.56
  text "+/-" at 12924,5618.48 h27.56
  text "+/-" at 13778,5618.48 h27.56
  text "REGISTRATION TOLERANCES:" at 11408.23,5617.42 h27.56
  text "METAL" at 12608,5617.42 h27.56
  text "5" at 13184.2,5617.42 h27.56
  text "3" at 14017.2,5617.42 h27.56
  text "MIL" at 14133.46,5617.42 h27.56
  text "HOLE SIZE TOLERANCE (UNLESS OTHERWISE SPECIFIED):" at 11408.23,5519.1 h27.56
  text "+/-" at 13778,5516.23 h27.56
  text "3" at 14017.2,5515.17 h27.56
  text "MIL" at 14133.46,5515.17 h27.56
  text "MATERIAL:" at 11333.46,5377.52 h27.56
  text "FR-4 High Tg" at 12319.9,5249 h27.56
  text "X" at 12175.46,5241.01 h27.56
  text "FR-408" at 11754.46,5236.49 h27.56
  text "OTHER" at 13242.46,5236.49 h27.56
  text "62 MIL (1.6mm) +/-10%" at 12074.56,5093.46 h27.56
  text "X" at 11954.46,5091.01 h27.56
  text "THICKNESS:" at 11408.23,5085.24 h27.56
  text "OTHER" at 13359.46,5085.24 h27.56
  text "TOLERANCE:" at 11408.23,4946.92 h27.56
  text "X" at 12256.46,4946.92 h27.56
  text "ANSI IPC-6012 TYPE 3 CLASS 2" at 12434.48,4946.92 h27.56
  text "OTHER +/-" at 12434.46,4802.73 h27.56
  text "BOW & TWIST:" at 11408.23,4657.54 h27.56
  text "X" at 12256.46,4657.54 h27.56
  text "ANSI IPC-6012 TYPE 3 CLASS 2" at 12434.48,4657.54 h27.56
  text "OTHER +/-" at 12434.46,4510.85 h27.56
  text "DRILLING:" at 11333.46,4380.23 h27.56
  text "NC_DRILL FILES" at 13094.46,4275.04 h27.56
  text "REFERENCE:" at 11408.23,4271.1 h27.56
  text "X" at 12065.46,4271.01 h27.56
  text "AS SHOWN" at 12243.46,4271.1 h27.56
  text "X" at 12966.46,4271.1 h27.56
  text "OTHER" at 13392.46,4128.85 h27.56
  text "PTH COPPER THICKNESS:" at 11407.91,4125.32 h27.56
  text "X" at 12547.14,4125.32 h27.56
  text "20-30 um" at 12675.14,4125.32 h27.56
  text "BOARD FINISH:" at 11333.46,3977.73 h27.56
  text "SILKSCREEN:" at 11488.68,3867.6 h27.56
  text "X" at 12446.46,3867.6 h27.56
  text "TOP" at 12563.46,3867.6 h27.56
  text "X" at 12956.46,3867.6 h27.56
  text "BOTTOM" at 13074.46,3867.6 h27.56
  text "SILKSCREEN COLOR:" at 11488.68,3712.41 h27.56
  text "X" at 12445.46,3712.41 h27.56
  text "WHITE" at 12563.46,3712.41 h27.56
  text "OTHER" at 13074.46,3712.41 h27.56
  text "X" at 12576.46,3568.96 h27.56
  text "GREEN" at 12694.46,3568.96 h27.56
  text "OTHER" at 13312.46,3568.96 h27.56
  text "SOLDER RESIST COLOR:" at 11488.68,3562.1 h27.56
  text "X" at 12576.46,3414.71 h27.56
  text "MATTE" at 12694.46,3414.71 h27.56
  text "SEMI-GLOSS" at 13312,3414.07 h27.56
  text "IMMERSION GOLD (ENIG)" at 12394.46,3241.94 h27.56
  text "ENEPIG" at 13732,3234.72 h27.56
  text "SURFACE FINISH:" at 11333.46,3233.72 h27.56
  text "X" at 12216.46,3233.72 h27.56
  text "IMM. TIN/SILVER OR EQUIV" at 11663,3096.4 h27.56
  text "OTHER" at 13094.46,3092.47 h27.56
  text "ARRAY/PANEL:" at 11333.46,2937.09 h27.56
  text "CUT AND TRIM PER M1 BOARD OUTLINE" at 12394.46,2928.87 h27.56
  text "N.C. ROUTE" at 12394.46,2792.9 h27.56
  text "X" at 13082.46,2792.9 h27.56
  text "V. SCORE" at 13260.46,2792.9 h27.56
  text "CERTIFICATION:" at 11333.46,2663.77 h27.56
  text "MATERIALS AND WORKMANSHIP FOR ALL PCBS" at 12058.46,2663.77 h27.56
  text "TO MEET OR EXCEED THE REQUIREMENTS OF:" at 12058.46,2569.71 h27.56
  text "X" at 11695.97,2441.08 h27.56
  text "ANSI IPC-A-600F CLASS ->" at 11823.96,2441.08 h27.56
  text "X" at 13471.97,2441.08 h27.56
  text "2" at 13581.96,2441.08 h27.56
  text "1" at 13266.96,2439.58 h27.56
  text "3" at 13935.96,2439.58 h27.56
  text "X" at 12507.97,2293.39 h27.56
  text "RoHS" at 12635.96,2293.39 h27.56
  text "OTHER" at 13280.36,2293.39 h27.56
  text "PER ORDER" at 13677.42,2293.39 h27.56
  text "ALL BOARDS MUST MEET OR EXCEED UL94-V0 REQUIREMENTS." at 11361,2139.57 h27.56
  text "PCB MUST BEAR THE UL94V-0 UL REGISTERED MATERIAL ID NUMBER" at 11361,2023.5 h27.56
  text "ADDITIONAL REQUIREMENTS:" at 11333.46,1854.08 h27.56
  text "MICROSECTION:" at 11408.23,1746.95 h27.56
  text "YES" at 12313.96,1746.95 h27.56
  text "REQUIRED" at 13175.46,1602.62 h27.56
  text "BARE BOARD ELEC. TEST:" at 11408.23,1599.76 h27.56
  text "NONE" at 12713.96,1599.76 h27.56
  text "X" at 13057.46,1599.76 h27.56
  text "PER ORDER" at 13767.46,1599.76 h27.56
  text "XX MIL VIAS REQUIRE CONDUCTIVE FILL AND PLANARIZE" at 11584.38,1290.84 h27.56
  text "OUTER XX MIL TRACES REQUIRE 50 OHM SINGLE-ENDED IMPEDANCE" at 11583.39,1127.46 h27.56
  text "LAYER 2 & 3 (INNER LAYERS) XX MIL WIDE, XX MIL SPACE / TRACES REQUIRE 100 OHM DIFFERENTIAL IMPEDANCE" at 11575.39,891.74 h27.56
  text ".Layer_Name" at 577,-858.49 h27.56
M11 Gerber Information:
  lines w10: -292,-930.17 6308,-930.17 ; -292,-726.83 6310,-726.83 ; -292,-523.5 -292,-1133.5 3713,-1133.5 6310,-1133.5 6310,-523.5 -291.5,-523.5 -291.5,-1133.5 1284,-1133.5 ; 2173,-1133.5 2173,-523.5 ; 3440,-726.83 3440,-523.5 ; 4280,-726.83 4280,-523.5 ; 4902,-1140 4902,-937.17
  text "ALL ARTWORK VIEWED FROM TOP SIDE" at -228.5,-655.67 h27.56
  text "BOARD #:" at 2248,-655.67 h27.56
  text ".PRJ_Number" at 2793.5,-655.67 h27.56
  text "REV:" at 3638,-655.67 h27.56
  text ".PCB_Rev" at 3929.5,-655.67 h27.56
  text "SVN REV:" at 4476,-655.67 h27.56
  text ".VersionControl_RevNumber" at 4982,-655.67 h27.56
  text "LAYER NAME =" at -228.5,-858.49 h27.56
  text "TID #:" at 2248,-859 h27.56
  text ".TID" at 2793.5,-859 h27.56
  text "PLOT NAME =" at -228.5,-1064.34 h27.56
  text ".plot_File_Name" at 577,-1064.34 h27.56
  text "GENERATED    :" at 2250,-1064.34 h27.56
  text ".Print_Date" at 3119.5,-1064.34 h27.56
  text ".Print_Time" at 3848.5,-1064.34 h27.56
  text "TEXAS INSTRUMENTS" at 5113,-1064.34 h27.56
M12 Stackup:
  drawing of 306 lines, arcs and shapes, not listed
  text "Layer" at 6637.65,7701.38 h27.56
  text "Name" at 6836.74,7701.38 h27.56
  text "Material" at 7274.6,7701.38 h27.56
  text "Thickness" at 7680.32,7701.38 h27.56
  text "Constant" at 7989.62,7701.38 h27.56
  text "Board Layer Stack" at 8262.18,7701.38 h27.56
  text "1" at 6637.65,7646.26 h27.56
  text "Top Overlay" at 6836.74,7646.26 h27.56
  text "2" at 6637.65,7591.15 h27.56
  text "Top Solder" at 6836.74,7591.15 h27.56
  text "Solder Resist" at 7274.6,7591.15 h27.56
  text "0.40mil" at 7680.32,7591.15 h27.56
  text "3.5" at 7989.62,7591.15 h27.56
  text "3" at 6637.65,7536.03 h27.56
  text "Top Layer" at 6836.74,7536.03 h27.56
  text "Copper" at 7274.6,7536.03 h27.56
  text "1.40mil" at 7680.32,7536.03 h27.56
  text "4" at 6637.65,7480.91 h27.56
  text "Dielectric1" at 6836.74,7480.91 h27.56
  text "370HR" at 7274.6,7480.91 h27.56
  text "18.60mil" at 7680.32,7480.91 h27.56
  text "4.2" at 7989.62,7480.91 h27.56
  text "5" at 6637.65,7425.79 h27.56
  text "PWR" at 6836.74,7425.79 h27.56
  text "Copper" at 7274.6,7425.79 h27.56
  text "1.42mil" at 7680.32,7425.79 h27.56
  text "6" at 6637.65,7370.67 h27.56
  text "Dielectric 2" at 6836.74,7370.67 h27.56
  text "370HR" at 7274.6,7370.67 h27.56
  text "18.60mil" at 7680.32,7370.67 h27.56
  text "4.2" at 7989.62,7370.67 h27.56
  text "7" at 6637.65,7315.56 h27.56
  text "GND" at 6836.74,7315.56 h27.56
  text "Copper" at 7274.6,7315.56 h27.56
  text "1.42mil" at 7680.32,7315.56 h27.56
  text "8" at 6637.65,7260.44 h27.56
  text "Dielectric 3" at 6836.74,7260.44 h27.56
  text "370HR" at 7274.6,7260.44 h27.56
  text "18.60mil" at 7680.32,7260.44 h27.56
  text "4.2" at 7989.62,7260.44 h27.56
  text "9" at 6637.65,7205.32 h27.56
  text "Bottom Layer" at 6836.74,7205.32 h27.56
  text "Copper" at 7274.6,7205.32 h27.56
  text "1.40mil" at 7680.32,7205.32 h27.56
  text "10" at 6637.65,7150.2 h27.56
  text "Bottom Solder" at 6836.74,7150.2 h27.56
  text "Solder Resist" at 7274.6,7150.2 h27.56
  text "0.40mil" at 7680.32,7150.2 h27.56
  text "3.5" at 7989.62,7150.2 h27.56
  text "11" at 6637.65,7095.08 h27.56
  text "Bottom Overlay" at 6836.74,7095.08 h27.56
  text ".Layer_Name" at 577,-858.49 h27.56
M13 Component Bodies Top:
  text ".Layer_Name" at 577,-858.49 h27.56
M14 Component Bodies Bottom:
  text ".Layer_Name" at 577,-858.49 h27.56
M15 Courtyards Top:
  text ".Layer_Name" at 577,-858.49 h27.56
M16 Courtyards Bottom:
  text ".Layer_Name" at 577,-858.49 h27.56
Drill Drawing:
  circle w10: c9010.83,7214.13 r22.14
  circle w10: c9010.83,7114.51 r13.28
  circle w10: c9010.83,7114.51 r22.14
  lines w10: 8988.69,6937.4 9032.97,6937.4 9010.83,6893.13 8988.69,6937.4 ; 8988.69,6992.75 9032.97,6992.75 9032.97,7037.03 8988.69,7037.03 8988.69,6992.75 ; 8988.69,7302.69 8999.76,7302.69 9010.83,7291.62 9021.9,7302.69 9032.97,7302.69 9021.9,7313.76 9032.97,7324.82 9021.9,7324.82 9010.83,7335.89 8999.76,7324.82 8988.69,7324.82 8999.76,7313.76 8988.69,7302.69 ; 8988.69,7402.31 8999.76,7402.31 8999.76,7391.24 9021.9,7391.24 9021.9,7402.31 9032.97,7402.31 9032.97,7424.45 9021.9,7424.45 9021.9,7435.52 8999.76,7435.52 8999.76,7424.45 8988.69,7424.45 8988.69,7402.31 ; 8988.69,7535.14 9032.97,7535.14 9010.83,7490.86 8988.69,7535.14 ; 8988.69,7590.48 9010.83,7601.55 9032.97,7590.48 9021.9,7612.62 9032.97,7634.76 9010.83,7623.69 8988.69,7634.76 8999.76,7612.62 8988.69,7590.48 ; 8997.54,6928.55 9024.11,6928.55 9010.83,6901.98 8997.54,6928.55 ; 8997.54,7001.61 9024.11,7001.61 9024.11,7028.17 8997.54,7028.17 8997.54,7001.61
  lines w12: 8947.93,6863.24 12060.87,6863.24 ; 8947.93,7660.22 12060.87,7660.22 ; 9263.56,6763.62 9263.56,7759.84 ; 9580.75,6763.62 9580.75,7759.84 ; 10202.49,6763.62 10202.49,7759.84 ; 10446.81,6763.62 10446.81,7759.84 ; 10807.15,6763.62 10807.15,7759.84 ; 11516.66,6763.62 11516.66,7759.84 ; 8947.93,6763.62 12060.87,6763.62 12060.87,7759.84 8947.93,7759.84 8947.93,6763.62
  text "Symbol" at 9007.7,7690.11 h72
  text "Quantity" at 9293.45,7690.11 h72
  text "Finished Hole Size" at 9610.63,7690.11 h72
  text "Plated" at 10232.38,7690.11 h72
  text "Hole Type" at 10476.7,7690.11 h72
  text "Drill Layer Pair" at 10837.04,7690.11 h72
  text "Hole Tolerance" at 11546.55,7690.11 h72
  text "4" at 9293.45,7590.48 h60
  text "96.00mil (2.438mm)" at 9610.63,7590.48 h60
  text "NPTH" at 10232.38,7590.48 h60
  text "Round" at 10476.7,7590.48 h60
  text "Top Layer - Bottom Layer" at 10837.04,7590.48 h60
  text "206" at 9293.45,7490.86 h60
  text "7.87mil (0.200mm)" at 9610.63,7490.86 h60
  text "PTH" at 10232.38,7490.86 h60
  text "Round" at 10476.7,7490.86 h60
  text "Top Layer - Bottom Layer" at 10837.04,7490.86 h60
  text "976" at 9293.45,7391.24 h60
  text "10.00mil (0.254mm)" at 9610.63,7391.24 h60
  text "PTH" at 10232.38,7391.24 h60
  text "Round" at 10476.7,7391.24 h60
  text "Top Layer - Bottom Layer" at 10837.04,7391.24 h60
  text "2" at 9293.45,7291.62 h60
  text "16.00mil (0.406mm)" at 9610.63,7291.62 h60
  text "PTH" at 10232.38,7291.62 h60
  text "Round" at 10476.7,7291.62 h60
  text "Top Layer - Bottom Layer" at 10837.04,7291.62 h60
  text "12" at 9293.45,7191.99 h60
  text "40.00mil (1.016mm)" at 9610.63,7191.99 h60
  text "PTH" at 10232.38,7191.99 h60
  text "Round" at 10476.7,7191.99 h60
  text "Top Layer - Bottom Layer" at 10837.04,7191.99 h60
  text "20" at 9293.45,7092.37 h60
  text "43.31mil (1.100mm)" at 9610.63,7092.37 h60
  text "PTH" at 10232.38,7092.37 h60
  text "Round" at 10476.7,7092.37 h60
  text "Top Layer - Bottom Layer" at 10837.04,7092.37 h60
  text "2" at 9293.45,6992.75 h60
  text "51.18mil (1.300mm)" at 9610.63,6992.75 h60
  text "PTH" at 10232.38,6992.75 h60
  text "Round" at 10476.7,6992.75 h60
  text "Top Layer - Bottom Layer" at 10837.04,6992.75 h60
  text "5" at 9293.45,6893.13 h60
  text "125.98mil (3.200mm)" at 9610.63,6893.13 h60
  text "PTH" at 10232.38,6893.13 h60
  text "Round" at 10476.7,6893.13 h60
  text "Top Layer - Bottom Layer" at 10837.04,6893.13 h60
  text "1227 Total" at 9293.45,6793.51 h60
  text ".Layer_Name" at 577,-858.49 h27.56
M17 Embedded Cavity:
  text ".Layer_Name" at 577,-858.49 h27.56
M18 Embedded Assembly:
  text ".Layer_Name" at 577,-858.49 h27.56
M19 Embedded Keepout:
  text ".Layer_Name" at 577,-858.49 h27.56

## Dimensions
0,-400 to 1000,-400 on M2 Board Dimensions
0,0 to 0,5518 on M2 Board Dimensions
0,0 to 11050,0 on M2 Board Dimensions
